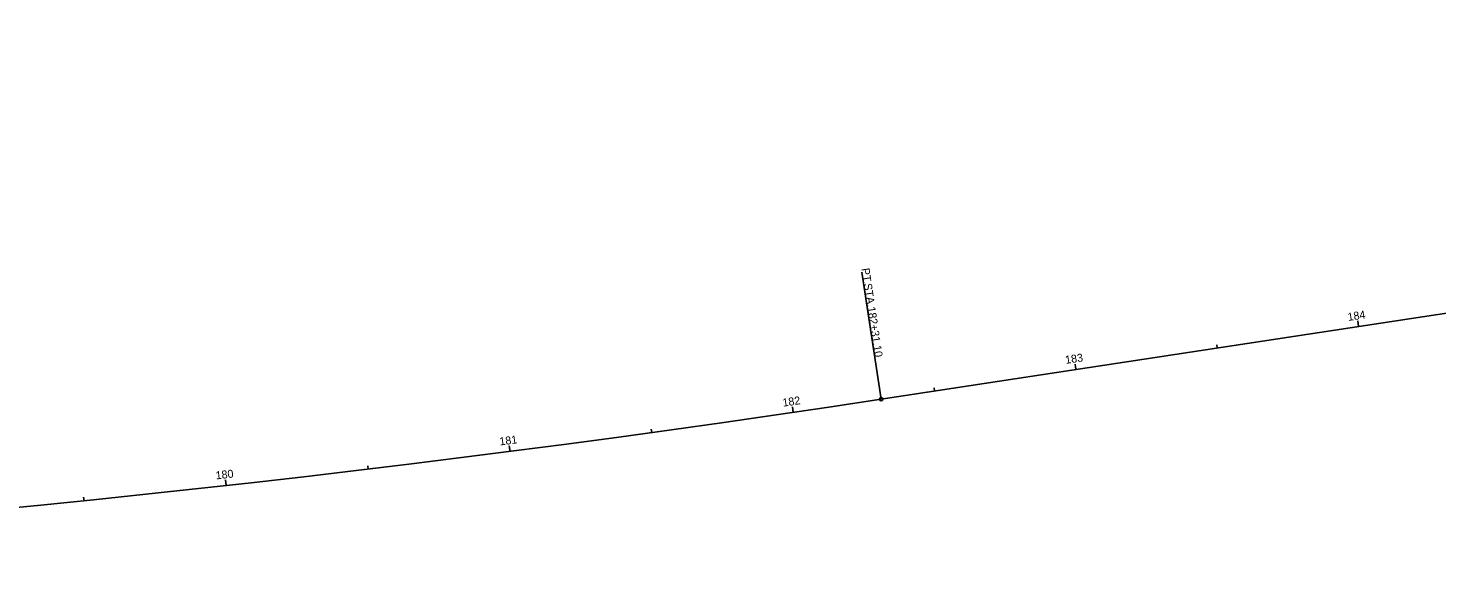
# Model space of a CAD drawing. Extents: x 1501024 to 1508874, y 327839 to 328839.
# Drawn here: x 1505916.2 to 1506408.9, y 328010.1 to 328205.2 of the extents above; entities that cross this region are included whole.
import ezdxf

# ---------------------------------------------------------------- set-up
doc = ezdxf.new("R2010")
doc.units = 0
for name, color, linetype in [('GE_X_Alignment', 7, 'Continuous'), ('GE_X_Alignment_100_Cardinal_Points', 7, 'Continuous'), ('GE_X_Alignment_100_Stations', 7, 'Continuous'), ('GE_X_Alignment_500_Cardinal_Points', 7, 'Continuous'), ('GE_X_Alignment_500_Stations', 7, 'Continuous')]:
    doc.layers.add(name, color=color, linetype=linetype)

msp = doc.modelspace()

# ---------------------------------------------------------------- linework, layer by layer
at = {"layer": 'GE_X_Alignment'}
msp.add_line((1506214.56, 328075.36), (1507019.33, 328197.87), dxfattribs=at)
msp.add_arc((1505352.29, 333739.68), 5729.58, 255.00563, 278.65563, dxfattribs=at)
at = {"layer": 'GE_X_Alignment_100_Cardinal_Points'}
msp.add_line((1506214.56, 328075.36), (1506207.79, 328119.84), dxfattribs=at)
msp.add_circle((1506214.56, 328075.36), 0.6, dxfattribs=at)
at = {"layer": 'GE_X_Alignment_100_Stations'}
for p, q in [((1506381.54, 328100.77), (1506381.24, 328102.75)), ((1506332.11, 328093.25), (1506331.93, 328094.44)), ((1506282.68, 328085.73), (1506282.38, 328087.7)), ((1506233.25, 328078.2), (1506233.06, 328079.39)), ((1506183.8, 328070.76), (1506183.51, 328072.74)), ((1506134.3, 328063.72), (1506134.14, 328064.91)), ((1506084.74, 328057.11), (1506084.48, 328059.09)), ((1506035.12, 328050.94), (1506034.98, 328052.13)), ((1505985.45, 328045.19), (1505985.23, 328047.18)), ((1505935.74, 328039.88), (1505935.61, 328041.08))]:
    msp.add_line(p, q, dxfattribs=at)
at = {"layer": 'GE_X_Alignment_500_Cardinal_Points'}
msp.add_line((1506214.56, 328075.36), (1506207.79, 328119.84), dxfattribs=at)
msp.add_circle((1506214.56, 328075.36), 0.6, dxfattribs=at)
at = {"layer": 'GE_X_Alignment_500_Stations'}
for p, q in [((1506381.54, 328100.77), (1506381.36, 328101.96)), ((1506282.68, 328085.73), (1506282.5, 328086.91)), ((1506183.8, 328070.76), (1506183.63, 328071.95)), ((1506084.74, 328057.11), (1506084.59, 328058.3)), ((1505985.45, 328045.19), (1505985.23, 328047.18))]:
    msp.add_line(p, q, dxfattribs=at)

# ---------------------------------------------------------------- texts
at = {"layer": 'GE_X_Alignment_100_Cardinal_Points'}
for s, p in [('PT', (1506207.65, 328121.05)), (' STA. ', (1506208.3, 328116.75)), ('182+31.10', (1506209.7, 328107.53))]:
    msp.add_text(s, height=2.8, rotation=278.6556, dxfattribs=at).set_placement(p)
at = {"layer": 'GE_X_Alignment_100_Stations'}
for s, rotation, p in [('184', 8.6556, (1506377.92, 328102.75)), ('183', 8.6556, (1506279.14, 328087.72)), ('182', 8.3446, (1506180.26, 328072.77)), ('181', 7.3446, (1506081.22, 328059.18)), ('180', 6.3446, (1505981.93, 328047.32))]:
    msp.add_text(s, height=2.8, rotation=rotation, dxfattribs=at).set_placement(p)
at = {"layer": 'GE_X_Alignment_500_Cardinal_Points'}
for s, p in [('PT', (1506207.65, 328121.05)), (' STA. ', (1506208.3, 328116.75)), ('182+31.10', (1506209.7, 328107.53))]:
    msp.add_text(s, height=2.8, rotation=278.6556, dxfattribs=at).set_placement(p)
at = {"layer": 'GE_X_Alignment_500_Stations'}
msp.add_text('180', height=2.8, rotation=6.3446, dxfattribs=at).set_placement((1505981.93, 328047.32))

doc.saveas('drawing.dxf')
